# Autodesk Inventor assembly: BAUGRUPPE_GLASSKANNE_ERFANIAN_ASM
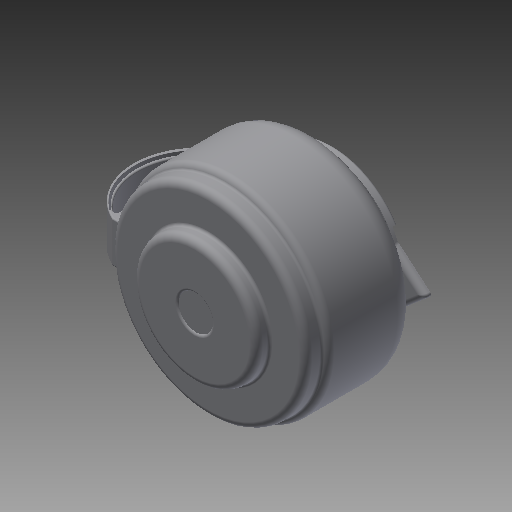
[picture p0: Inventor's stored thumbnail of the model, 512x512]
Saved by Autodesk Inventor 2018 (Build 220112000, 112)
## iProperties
Created: 2019-01
Part Number: BAUGRUPPE_GLASSKANNE_ERFANIAN_ASM
Material: Generisch
Document SubType Name: Assembly
Designer: zand
Author: zand
Revision Number: 14LAST_VERSION
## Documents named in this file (4)
- W:\KAFFEEMASCHINE\Creo5-STEP-Inventor\STEP\BAUGRUPPE_GLASSKANNE_ERFANIAN_ASM.iam
- W:\KAFFEEMASCHINE\Creo5-STEP-Inventor\STEP\GLASSKANNE_ERFANIAN.ipt
- W:\KAFFEEMASCHINE\Creo5-STEP-Inventor\STEP\HANDGRIFF_ERFANIAN_AF0.ipt
- W:\KAFFEEMASCHINE\Creo5-STEP-Inventor\STEP\GLASSKANNEDECKEL_ERFANIAN_AF0.ipt
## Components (3 placed, 3 different names)
1. Glaskanne
2. Handgriff
3. Glaskannendeckel
